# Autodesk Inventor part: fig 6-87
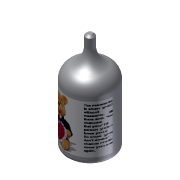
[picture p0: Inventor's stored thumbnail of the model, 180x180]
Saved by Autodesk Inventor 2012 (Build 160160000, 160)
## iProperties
Shininess: 64.0
Length Units: 11269
Angle Units: 11279
Time Units: 11290
Mass Units: 11283
Length Display Precision: 3
Angle Display Precision: 2
Compacted: True
Part Number: fig 6-87
Document SubType Name: Modeling
Created: 2002-12
Designer: deepak
Density: 1 g/cm^3
Material: Default
Density: 0.0
Volumn: 0.0
Area: 0.0
PropertySet Name: Model Information
Control State: 0
Master: False
Checked Out: False
Author: deepak
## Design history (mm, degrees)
node "Sketch1"
sketch "Sketch2"
  geometry: L1 (2.054, 26.655)-(2.054, 21.177); L2 (11.64, 6.114)-(11.64, -24.209); L3 (11.64, -24.209)-(-0.098, -24.209); L4 (-0.098, -24.209)-(-0.098, 26.655); L5 (-0.098, 26.655)-(2.054, 26.655); A1 r 9.502 centre (11.556, 21.177) between (2.054, 21.177) and (7.532, 12.57); A2 r 7.127 centre (4.514, 6.114) between (11.64, 6.114) and (7.532, 12.57)
  constraints: 10 end point, 4 point on circle, 3 parallel, 3 tangent, 2 centre point, 1 perpendicular, 1 vertical
revolve "Revolution1" sketch "Sketch2" stored, may be unused: angle "d0" = 90 deg
fillet "Fillet1" dims "d1" = 2
chamfer "Chamfer1" distance "d2" = 1; stored, may be unused: second distance "d3" = 2, angle "d21" = 45 deg
workplane "Work Plane1"
workplane "Work Plane2"
sketch "Sketch3"
  geometry: L1 (-18.179, 13.331)-(17.364, 13.331); L2 (17.364, 13.331)-(17.364, -11.702); L3 (17.364, -11.702)-(-18.179, -11.702); L4 (-18.179, -11.702)-(-18.179, 13.331); 1 other entity
  constraints: 2 other
feature "Decal3" sketch "Sketch3"
body "Solid1"
node "Image2"
other parameters: "d4" = -8
